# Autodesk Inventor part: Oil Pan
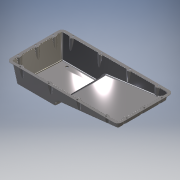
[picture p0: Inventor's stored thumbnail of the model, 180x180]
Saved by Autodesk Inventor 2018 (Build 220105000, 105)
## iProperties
Shininess: 25.0
Length Units: 11269
Angle Units: 11279
Time Units: 11290
Mass Units: 11286
Length Display Precision: 3
Angle Display Precision: 2
Compacted: True
Company: Autodesk, Inc.
Created: 2000-11
Part Number: Oil Pan
Document SubType Name: Modeling
Designer: Autodesk, Inc.
Density: 1 g/cm^3
Mass: 268.575 g
Surface Area: 4246.09 cm^2
Volume: 268.575 cm^3
Material: Generic
Appearance: Metal-AL-6061 (Polished)
Density: 0.0
Volumn: 0.0
Area: 0.0
PropertySet Name: Model Information
Control State: 0
Master: False
Checked Out: False
Author: Autodesk, Inc.
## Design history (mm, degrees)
sketch "Sketch2"
  geometry: L1 (-254, 127)-(254, 127); L2 (254, 127)-(254, -127); L3 (254, -127)-(-254, -127); L4 (-254, -127)-(-254, 127); L5 (0, 0)-(0, -127); L6 (0, 0)-(-254, 0)
  constraints: 12 end point, 3 perpendicular, 2 midpoint, 2 parallel, 1 horizontal
  dimensions: "d0" = 508 distance of L2.end L3.end; "d1" = 254 distance of L1.end L2.end
extrude "Extrusion1" new body sketch "Sketch2" distance "d2" = 76.2; taper "d3" = 0 deg
sketch "Sketch3"
  geometry: L1 (-254, -127)-(-254, 127) reference; L2 (254, -127)-(-254, -127) reference; L3 (-254, 127)-(-50.8, 127); L4 (-50.8, 127)-(-50.8, -127); L5 (-50.8, -127)-(-254, -127); L6 (-254, -127)-(-254, 127)
  constraints: 8 end point, 2 parallel, 1 horizontal, 1 perpendicular, 1 point on line
  dimensions: "d4" = 203.2 distance of L1.end L3.end
extrude "Extrusion2" join sketch "Sketch3" distance "d5" = 38.1; taper "d6" = 0 deg
sketch "Sketch4"
  geometry: L1 (-254, -127)-(-254, 127) reference; L2 (-50.8, 127)-(-50.8, -127) reference; L3 (-50.8, -76.2)-(-254, -76.2); L4 (-50.8, -127)-(-254, -127) reference
  constraints: 2 end point, 2 point on line, 1 perpendicular
  dimensions: "d17" = 50.8 distance between parallel lines of L3 L4
split "Split1" sketch "Sketch4"
fillet "Fillet4" dims "d18" = 127
fillet "Fillet1" dims "d9" = 19.05
fillet "Fillet2" dims "d10" = 19.05
shell "Shell1" dims "d11" = 12.7
sketch "Sketch15" dims "d118" = 10, "d137" = 10
  geometry: L1 (-235.092, 127)-(235.092, 127) reference; L2 (-254, -108.092)-(-254, 108.092) reference; L3 (235.092, -127)-(-235.092, -127) reference; L4 (254, 108.092)-(254, -108.092) reference; L5 (247.5, 108.092)-(247.5, -108.092); L6 (235.092, -120.5)-(-235.092, -120.5); L7 (-247.5, -108.092)-(-247.5, 108.092); L8 (-235.092, 120.5)-(235.092, 120.5); L9 (-361.106, 0)-(361.106, 0) reference; L10 (-210.2, 120.5)-(-184.8, 120.5); L11 (-80.2, 120.5)-(-54.8, 120.5); L12 (49.8, 120.5)-(75.2, 120.5); L13 (179.8, 120.5)-(205.2, 120.5); L14 (-247.5, 12.7)-(-247.5, -12.7); L15 (-247.5, 92.7)-(-247.5, 67.3); L16 (-247.5, -92.7)-(-247.5, -67.3); A1 r 12.7 centre (-197.5, 120.5) between (-210.2, 120.5) and (-184.8, 120.5); A2 r 12.7 centre (-67.5, 120.5) between (-80.2, 120.5) and (-54.8, 120.5); A3 r 12.7 centre (62.5, 120.5) between (49.8, 120.5) and (75.2, 120.5); A4 r 12.7 centre (192.5, 120.5) between (179.8, 120.5) and (205.2, 120.5); A5 r 12.7 centre (-247.5, 0) between (-247.5, -12.7) and (-247.5, 12.7); A6 r 12.7 centre (-247.5, 80) between (-247.5, 67.3) and (-247.5, 92.7); A7 r 12.7 centre (-247.5, -80) between (-247.5, -92.7) and (-247.5, -67.3); 10 further points; 3 other entities
  constraints: 22 end point, 17 point on circle, 7 centre point, 7 coincident, 6 point on line, 5 collinear, 5 parallel, 5 symmetric about line, 1 horizontal, 1 midpoint, 1 vertical, 35 other
  dimensions: "d110" = 6.5 distance between parallel lines of L1 L8; "d111" = 50 distance from line of point (-197.5, 120.5) L7; "d112" = 12.7 radius of A1; "d115" = 130 distance of A1.centre A2.centre; "d121" = 12.7 radius of A5 (derived); "d129" = 120.5 vertical distance of point (-197.5, 120.5) point (-247.5, 0) (derived); "d134" = 80 distance of A5.centre A6.centre
extrude "Extrusion10" join sketch "Sketch15" stored distance "d130" = 10; taper "d131" = 0 deg
mirror "Mirror1"
extrude "Extrusion11" join sketch "Sketch15" stored distance "d139" = 10; taper "d140" = 0 deg
mirror "Mirror2"
shell "Shell5" dims "d91" = 1.27
fillet "Fillet10" dims "d52" = 3.81, "d102" = 5.099 (derived)
sketch "Sketch16"
  geometry: A1 r 12.7 centre (-247.5, 80) between (-239.705, 69.974) and (-239.705, 90.026) reference; A2 r 12.7 centre (-197.5, 120.5) between (-207.526, 112.705) and (-187.474, 112.705) reference; A3 r 12.7 centre (-67.5, 120.5) between (-77.526, 112.705) and (-57.474, 112.705) reference; A4 r 12.7 centre (62.5, 120.5) between (52.474, 112.705) and (72.526, 112.705) reference; A5 r 12.7 centre (192.5, 120.5) between (182.474, 112.705) and (202.526, 112.705) reference; A6 r 12.7 centre (247.5, 80) between (239.705, 90.026) and (239.705, 69.974) reference; A7 r 12.7 centre (247.5, 0) between (239.705, 10.026) and (239.705, -10.026) reference; A8 r 12.7 centre (247.5, -80) between (239.705, -69.974) and (239.705, -90.026) reference; A9 r 12.7 centre (192.5, -120.5) between (202.234, -112.343) and (182.766, -112.343) reference; A10 r 12.7 centre (62.5, -120.5) between (72.526, -112.705) and (52.474, -112.705) reference; A11 r 12.7 centre (-67.5, -120.5) between (-57.474, -112.705) and (-77.526, -112.705) reference; A12 r 12.7 centre (-197.5, -120.5) between (-187.474, -112.705) and (-207.526, -112.705) reference; A13 r 12.7 centre (-247.5, -80) between (-239.705, -90.026) and (-239.705, -69.974) reference; A14 r 12.7 centre (-247.5, 0) between (-239.705, -10.026) and (-239.705, 10.026) reference
hole "Hole4" sketch "Sketch16" at (-247.5, 0), (-247.5, 80), (-247.5, -80), (-197.5, 120.5), (-67.5, 120.5), (62.5, 120.5), (192.5, 120.5), (247.5, 80), (247.5, 0), (247.5, -80), (192.5, -120.5), (62.5, -120.5)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 diameter "d141" = 6.35; stored, may be unused: countersink angle "d145" = 90 deg, drill point angle "d147" = 118 deg; dims "d142" = 6, "d143" = 4, "d144" = 2, "d146" = 8
fillet "Fillet15" dims "d100" = 0.508, "d101" = 1.797 (derived)
sketch "Sketch14"
  geometry: L1 (158.973, 0)-(0, 0) reference; L2 (0, 16.586)-(158.973, 16.586) reference; C1 r 8.293 at (30.612, 8.293); C2 r 3.175 at (-24.388, 96.112) reference
  constraints: 2 tangent, 1 centre point
  dimensions: "d148" = 55 horizontal distance of C1.centre C2.centre
extrude "Extrusion9" join sketch "Sketch14" distance "d105" = 3.81; taper "d106" = 0 deg
fillet "Fillet13" dims "d64" = 1.905 (derived)
sketch "Sketch12"
  geometry: C1 r 7.168 at (0, 0); C2 r 6.388 at (0, 0) reference; 1 further point
  constraints: 1 centre point, 1 coincident
hole "Hole2" sketch "Sketch12" at (0, 0) diameter "d65" = 10.414; stored, may be unused: countersink angle "d68" = 60 deg, drill point angle "d70" = 118 deg; dims "d66" = 9.525, "d67" = 6.35, "d69" = 19.05, "d107" = 12.7
body "Solid1"
feature "FaceDraft1" dims angle "d7" = 20 deg
feature "FaceDraft5" dims angle "d16" = 3 deg
feature "FaceDraft4" dims angle "d15" = 7 deg
feature "FaceDraft7" dims angle "d42" = 7 deg
other parameters: "d73" = 12.7, "Thickness" = 1.289 [user parameter]
